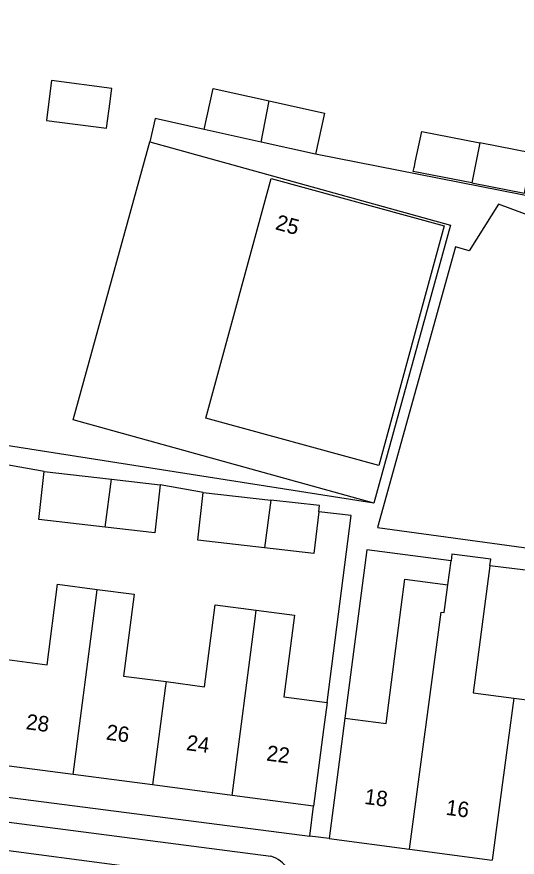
# Model space of a CAD drawing. Extents: x 161845 to 162341, y 381620 to 382158.
# Drawn here: x 161968.8 to 162001.2, y 381704.8 to 381759.2 of the extents above; entities that cross this region are included whole.
import ezdxf

# ---------------------------------------------------------------- set-up
doc = ezdxf.new("R2010")
doc.units = 0
for name, color, linetype in [('IMGEO_Pand', 7, 'Continuous'), ('IMGEO_Pand_nummerreeks', 7, 'Continuous'), ('IMGEO_Pand_vergunning_verleend', 7, 'Continuous'), ('IMGEO_Rijbaan_lokaal_open', 7, 'Continuous'), ('IMGEO_Voetpad_open', 7, 'Continuous')]:
    doc.layers.add(name, color=color, linetype=linetype)

msp = doc.modelspace()

# ---------------------------------------------------------------- linework, layer by layer
at = {"layer": 'IMGEO_Pand'}
for points in [[(161974.96, 381754.523), (161971.054, 381755.029), (161971.013, 381754.712), (161970.72, 381752.445), (161974.625, 381751.939), (161974.849, 381753.666), (161974.919, 381754.206), (161974.96, 381754.523)], [(161980.942, 381751.867), (161981.534, 381754.52), (161985.159, 381753.711)], [(161984.634, 381751.043), (161985.159, 381753.711)], [(161985.159, 381753.711), (161988.743, 381752.912), (161988.151, 381750.259)], [(161984.634, 381751.043), (161980.942, 381751.867)], [(161998.285, 381748.408), (161994.488, 381749.153), (161994.54, 381749.402), (161994.557, 381749.478), (161994.613, 381749.745), (161995.034, 381751.733), (161998.795, 381750.995)], [(161991.926, 381727.689), (161972.452, 381733.08), (161977.428, 381751.055)], [(161977.428, 381751.055), (161996.902, 381745.663), (161991.926, 381727.689)], [(161988.151, 381750.259), (161984.634, 381751.043)], [(161998.795, 381750.995), (161998.285, 381748.408)], [(161998.285, 381748.408), (162001.694, 381747.739), (162002.202, 381750.327), (161998.795, 381750.995)], [(162024.059, 381736.377), (162003.547, 381745.723), (162000, 381747.039), (161998.107, 381744.019), (161997.212, 381744.268), (161992.167, 381726.115), (162012.543, 381723.321)], [(161974.539, 381726.139), (161970.224, 381726.63), (161970.576, 381729.729)], [(161970.576, 381729.729), (161974.942, 381729.232)], [(161974.539, 381726.139), (161974.942, 381729.232)], [(161974.942, 381729.232), (161978.103, 381728.872)], [(161978.103, 381728.872), (161977.75, 381725.774), (161974.539, 381726.139)], [(161984.846, 381724.791), (161980.529, 381725.282), (161980.881, 381728.381)], [(161980.881, 381728.381), (161985.251, 381727.884)], [(161985.251, 381727.884), (161984.846, 381724.791)], [(161988.362, 381727.119), (161988.408, 381727.524), (161985.251, 381727.884)], [(161988.362, 381727.119), (161988.055, 381724.426), (161984.846, 381724.791)], [(161999.444, 381723.63), (161999.5, 381724.063), (161996.988, 381724.391), (161996.932, 381723.958)], [(161996.728, 381722.396), (161996.932, 381723.958)], [(161999.444, 381723.63), (161998.371, 381715.405), (162000, 381715.198), (162000.991, 381715.072)], [(161968.178, 381717.561), (161970.769, 381717.223), (161971.448, 381722.434), (161974.011, 381722.1)], [(161990.054, 381713.77), (161992.728, 381713.422), (161993.711, 381720.964), (161993.945, 381722.758), (161996.728, 381722.396)], [(162000.991, 381715.072), (162003.709, 381714.726), (162004.567, 381721.164), (162004.796, 381722.881), (162007.243, 381722.562), (162007.089, 381721.399)], [(161972.448, 381710.122), (161973.94, 381721.553), (161974.011, 381722.1)], [(161974.011, 381722.1), (161976.41, 381721.787), (161975.72, 381716.496), (161978.474, 381716.137)], [(161994.25, 381705.292), (161996.286, 381720.629), (161996.494, 381720.602), (161996.728, 381722.396)], [(161978.474, 381716.137), (161980.971, 381715.811), (161981.663, 381721.117), (161984.319, 381720.77)], [(161982.754, 381708.778), (161984.245, 381720.205), (161984.319, 381720.77)], [(161984.319, 381720.77), (161986.802, 381720.446), (161986.112, 381715.156), (161988.901, 381714.793)], [(161978.474, 381716.137), (161978.419, 381715.714), (161977.601, 381709.45)], [(162000.991, 381715.072), (162000.627, 381712.34), (162000, 381707.674), (161999.589, 381704.582)], [(161988.901, 381714.793), (161988.674, 381713.049), (161988.027, 381708.09)], [(161990.054, 381713.77), (161989.686, 381710.944), (161989.039, 381705.985)], [(161972.448, 381710.122), (161967.295, 381710.794)], [(161977.601, 381709.45), (161972.448, 381710.122)], [(161982.754, 381708.778), (161977.601, 381709.45)], [(161988.027, 381708.09), (161982.754, 381708.778)], [(161989.039, 381705.985), (161994.25, 381705.292)], [(161994.25, 381705.292), (161999.589, 381704.582)]]:
    msp.add_lwpolyline(points, dxfattribs=at)
at = {"layer": 'IMGEO_Pand_vergunning_verleend'}
msp.add_lwpolyline([(161981.052, 381733.177), (161985.285, 381748.692), (161996.486, 381745.635), (161992.252, 381730.121), (161981.052, 381733.177)], dxfattribs=at)
at = {"layer": 'IMGEO_Rijbaan_lokaal_open'}
msp.add_lwpolyline([(161956.834, 381706.713), (161986.241, 381702.838)], dxfattribs=at)
at = {"layer": 'IMGEO_Voetpad_open'}
for points in [[(162007.054, 381759.154), (162005.486, 381746.869), (161988.151, 381750.259)], [(161980.942, 381751.867), (161977.767, 381752.576), (161977.428, 381751.055)], [(161991.926, 381727.689), (161961.501, 381732.448)], [(161970.576, 381729.729), (161967.797, 381730.219)], [(161980.881, 381728.381), (161978.103, 381728.872)], [(161988.901, 381714.793), (161990.474, 381726.878), (161988.362, 381727.119)], [(161996.932, 381723.958), (161991.473, 381724.669), (161990.054, 381713.77)], [(162012.365, 381722.027), (162007.983, 381722.598), (161999.444, 381723.63)], [(161956.476, 381710.172), (161987.777, 381706.147)], [(161959.136, 381708.231), (161985.254, 381704.84)], [(161987.777, 381706.147), (161988.027, 381708.09)], [(161989.039, 381705.985), (161987.777, 381706.147)]]:
    msp.add_lwpolyline(points, dxfattribs=at)
msp.add_arc((161984.809, 381703.139), 1.758, 28.7211, 75.3483, dxfattribs=at)

# ---------------------------------------------------------------- texts
at = {"layer": 'IMGEO_Pand_nummerreeks'}
for s, rotation, p in [('25', 344.5235, (161985.496, 381745.418)), ('28', 352.5703, (161969.362, 381713.065)), ('26', 352.5703, (161974.552, 381712.389)), ('24', 352.5703, (161979.745, 381711.711)), ('22', 352.5703, (161984.935, 381711.034)), ('18', 352.4198, (161991.283, 381708.229)), ('16', 352.4198, (161996.555, 381707.527))]:
    msp.add_text(s, height=1, rotation=rotation, dxfattribs=at).set_placement(p)

doc.saveas('drawing.dxf')
